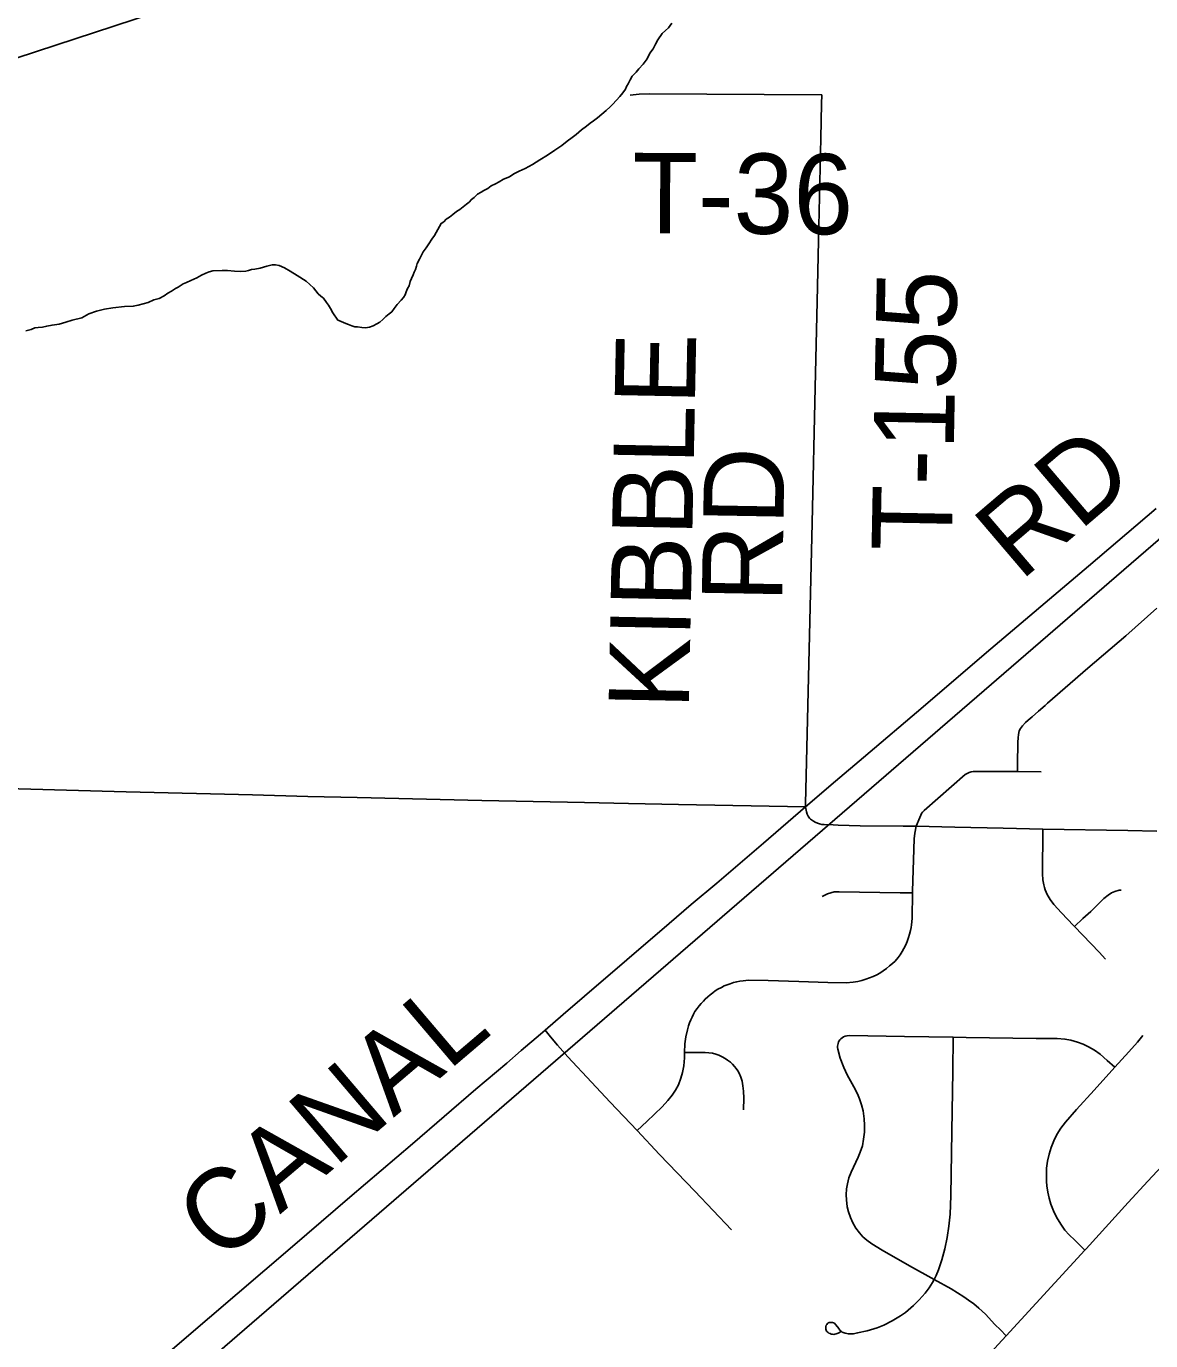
# Model space of a CAD drawing. Extents: x -483 to 680, y 0 to 440.
# Drawn here: x 200.49 to 240.28, y 283.88 to 330.39 of the extents above; entities that cross this region are included whole.
import ezdxf

# ---------------------------------------------------------------- set-up
doc = ezdxf.new("R2010")
doc.units = 0
for name, color, linetype in [('GM_X_City_Street', 7, 'Continuous'), ('GM_X_County_Road', 7, 'Continuous'), ('GM_X_County_Road_Text', 7, 'Continuous'), ('GM_X_Minor_River', 7, 'Continuous'), ('GM_X_Rail_Line', 7, 'Continuous'), ('GM_X_State_Route', 7, 'Continuous'), ('GM_X_Township_Road', 7, 'Continuous'), ('GM_X_Township_Road_Text', 7, 'Continuous')]:
    doc.layers.add(name, color=color, linetype=linetype)

msp = doc.modelspace()

# ---------------------------------------------------------------- linework, layer by layer
at = {"layer": 'GM_X_City_Street'}
for points in [[(235.562, 304.018), (235.565, 304.383), (235.569, 304.938), (235.576, 305.061), (235.584, 305.214), (235.596, 305.337), (235.627, 305.457), (235.665, 305.541), (235.737, 305.643), (235.845, 305.754), (235.936, 305.835), (236.076, 305.956), (236.31, 306.16), (236.536, 306.363), (236.626, 306.441), (238.047, 307.678), (239.394, 308.823), (240.497, 309.804)], [(231.975, 302.085), (232.102, 302.398), (232.143, 302.484), (232.172, 302.533), (232.205, 302.583), (232.258, 302.64), (233.713, 303.912), (233.783, 303.957), (233.849, 303.986), (233.923, 304.007), (233.992, 304.02), (234.095, 304.023), (235.107, 304.024), (235.562, 304.018), (236.396, 304.007)], [(228.062, 302.769), (228.096, 302.594), (228.121, 302.517), (228.16, 302.439), (228.209, 302.369), (228.239, 302.339), (228.272, 302.312), (228.345, 302.265), (228.408, 302.229), (228.485, 302.194), (228.559, 302.169), (228.64, 302.152), (228.721, 302.145), (229.039, 302.132), (229.214, 302.123), (229.993, 302.105), (231.516, 302.089), (231.975, 302.085), (233.349, 302.054), (235.058, 302.014), (236.465, 301.988), (239.471, 301.934), (240.496, 301.913)], [(222.109, 291.316), (222.45, 291.643), (222.988, 292.158), (223.197, 292.383), (223.349, 292.575), (223.466, 292.753), (223.564, 292.942), (223.655, 293.168), (223.712, 293.373), (223.754, 293.614), (223.776, 293.889), (223.784, 294.083), (223.796, 294.387), (223.828, 294.638), (223.882, 294.885), (223.923, 295.022), (223.958, 295.127), (224.002, 295.233), (224.049, 295.33), (224.099, 295.439), (224.152, 295.529), (224.228, 295.635), (224.302, 295.732), (224.371, 295.816), (224.448, 295.899), (224.512, 295.969), (224.607, 296.054), (224.686, 296.121), (224.781, 296.192), (224.871, 296.258), (224.963, 296.321), (225.086, 296.385), (225.189, 296.435), (225.398, 296.514), (225.516, 296.552), (225.629, 296.585), (225.74, 296.605), (225.86, 296.622), (226.051, 296.636), (226.737, 296.624), (227.825, 296.59), (228.85, 296.562), (229.501, 296.55), (229.744, 296.567), (229.909, 296.589), (230.051, 296.624), (230.201, 296.671), (230.326, 296.717), (230.452, 296.768), (230.583, 296.828), (230.694, 296.892), (230.813, 296.968), (230.926, 297.052), (231.039, 297.145), (231.138, 297.231), (231.229, 297.316), (231.337, 297.441), (231.413, 297.542), (231.487, 297.657), (231.547, 297.764), (231.609, 297.89), (231.655, 298.011), (231.709, 298.155), (231.746, 298.272), (231.781, 298.4), (231.801, 298.505), (231.814, 298.597), (231.828, 298.71), (231.836, 298.829), (231.851, 299.727), (231.852, 299.787), (231.904, 301.638), (231.93, 301.838), (231.975, 302.085)], [(238.682, 297.383), (238.447, 297.63), (237.575, 298.539), (237.544, 298.571), (237.116, 299.019), (236.849, 299.318), (236.724, 299.49), (236.618, 299.673), (236.546, 299.838), (236.518, 299.917), (236.493, 300.012), (236.46, 300.19), (236.442, 300.401), (236.446, 300.771), (236.458, 301.579), (236.465, 301.988)], [(228.652, 299.595), (228.841, 299.691), (228.954, 299.736), (229.072, 299.76), (229.258, 299.769), (231.408, 299.734), (231.851, 299.727)], [(237.575, 298.539), (237.88, 298.822), (238.152, 299.075), (238.622, 299.525), (238.765, 299.643), (238.894, 299.727), (239.007, 299.777), (239.157, 299.819), (239.226, 299.83)], [(225.448, 287.803), (224.146, 289.178), (222.901, 290.477), (222.109, 291.316), (221.154, 292.327), (220.495, 293.028), (219.655, 293.932), (219.285, 294.335), (219.042, 294.631), (218.846, 294.87)], [(229.308, 284.207), (229.27, 284.177), (229.221, 284.148), (229.188, 284.135), (229.144, 284.123), (229.098, 284.114), (229.059, 284.109), (229.013, 284.112), (228.966, 284.12), (228.929, 284.133), (228.892, 284.149), (228.861, 284.17), (228.832, 284.194), (228.81, 284.225), (228.794, 284.254), (228.784, 284.29), (228.78, 284.322), (228.782, 284.356), (228.786, 284.391), (228.797, 284.431), (228.815, 284.463), (228.838, 284.49), (228.869, 284.512), (228.901, 284.526), (228.94, 284.533), (228.978, 284.533), (229.018, 284.529), (229.052, 284.52), (229.083, 284.505), (229.129, 284.463), (229.196, 284.37), (229.238, 284.313), (229.267, 284.274), (229.31, 284.228), (229.335, 284.205), (229.363, 284.187), (229.396, 284.171), (229.426, 284.157), (229.467, 284.145), (229.525, 284.133), (229.577, 284.126), (229.627, 284.123), (229.676, 284.123), (229.761, 284.132), (229.907, 284.159), (230.241, 284.235), (230.598, 284.341), (230.829, 284.433), (231.133, 284.589), (231.429, 284.76), (231.605, 284.887), (231.888, 285.13), (232.086, 285.327), (232.291, 285.561), (232.44, 285.76), (232.555, 285.944), (232.612, 286.051), (232.685, 286.191), (232.77, 286.391), (232.885, 286.746), (232.988, 287.136), (233.072, 287.532), (233.133, 287.931), (233.177, 288.364), (233.209, 289.014), (233.242, 291.282), (233.27, 293.426), (233.287, 294.625)], [(235.164, 284.056), (234.96, 284.263), (234.764, 284.463), (234.428, 284.826), (234.192, 285.041), (234.015, 285.186), (233.835, 285.319), (233.664, 285.434), (233.212, 285.714), (232.612, 286.051), (231.746, 286.537), (230.775, 287.092), (230.404, 287.315), (230.231, 287.439), (230.096, 287.56), (229.975, 287.695), (229.848, 287.867), (229.74, 288.05), (229.652, 288.244), (229.581, 288.444), (229.54, 288.621), (229.508, 288.863), (229.501, 289.045), (229.514, 289.258), (229.544, 289.437), (229.598, 289.643), (229.672, 289.843), (229.929, 290.373), (230.001, 290.551), (230.074, 290.782), (230.114, 291.011), (230.144, 291.262), (230.155, 291.514), (230.143, 291.736), (230.099, 292.017), (230.047, 292.233), (229.975, 292.442), (229.903, 292.616), (229.774, 292.868), (229.54, 293.293), (229.415, 293.555), (229.29, 293.877), (229.204, 294.195), (229.199, 294.253), (229.199, 294.3), (229.204, 294.357), (229.212, 294.401), (229.235, 294.458), (229.277, 294.526), (229.315, 294.561)], [(229.315, 294.561), (229.358, 294.599), (229.407, 294.635), (229.465, 294.66), (229.531, 294.676), (229.613, 294.687), (231.569, 294.653), (233.287, 294.625), (233.742, 294.617), (236.225, 294.582), (236.968, 294.573), (237.243, 294.555), (237.452, 294.517), (237.687, 294.452), (237.887, 294.378), (238.079, 294.287), (238.288, 294.162), (238.485, 294.019), (238.739, 293.794), (239.005, 293.559)], [(237.947, 287.086), (237.588, 287.437), (237.386, 287.634), (237.24, 287.8), (237.093, 288.007), (236.948, 288.25), (236.837, 288.477), (236.744, 288.711), (236.68, 288.924), (236.634, 289.14), (236.604, 289.358), (236.591, 289.514), (236.583, 289.734), (236.584, 289.828), (236.594, 289.986), (236.628, 290.236), (236.681, 290.482), (236.753, 290.724), (236.846, 290.96), (236.96, 291.185), (237.094, 291.398), (237.263, 291.62), (237.651, 292.062), (238.272, 292.751), (239.005, 293.559), (239.501, 294.106), (239.807, 294.449), (240.003, 294.678)], [(225.869, 292.048), (225.882, 292.464), (225.873, 292.713), (225.85, 292.907), (225.818, 293.07), (225.773, 293.209), (225.71, 293.345), (225.662, 293.437), (225.61, 293.512), (225.55, 293.588), (225.482, 293.664), (225.403, 293.737), (225.306, 293.81), (225.221, 293.868), (225.108, 293.929), (224.995, 293.983), (224.885, 294.026), (224.77, 294.056), (224.647, 294.07), (224.515, 294.078), (224.207, 294.08), (223.784, 294.083)]]:
    msp.add_lwpolyline(points, dxfattribs=at)
at = {"layer": 'GM_X_County_Road'}
for points in [[(228.062, 302.769), (229.121, 303.679), (230.118, 304.522), (232.226, 306.314), (234.469, 308.236), (238.071, 311.294), (240.468, 313.323)], [(218.846, 294.87), (219.488, 295.426), (220.246, 296.07), (223.238, 298.646), (224.018, 299.314), (224.922, 300.074), (226.574, 301.491), (228.062, 302.769)], [(199.794, 278.543), (201.845, 280.377), (203.117, 281.425), (204.923, 282.948), (206.976, 284.71), (209.908, 287.214), (211.937, 288.957), (214.16, 290.855), (216.4, 292.781), (217.497, 293.705), (218.002, 294.15), (218.689, 294.733), (218.846, 294.87)]]:
    msp.add_lwpolyline(points, dxfattribs=at)
at = {"layer": 'GM_X_Minor_River'}
for points in [[(195.284, 273.119), (289.59, 354.596)], [(223.328, 330.503), (223.209, 330.335), (223.112, 330.243), (222.996, 330.132), (222.838, 329.908), (222.758, 329.758), (222.678, 329.589), (222.56, 329.44), (222.46, 329.234), (222.323, 329.047), (222.167, 328.88), (222.069, 328.769), (221.932, 328.62), (221.853, 328.49), (221.793, 328.358), (221.733, 328.265), (221.693, 328.171), (221.595, 328.04), (221.496, 327.91), (221.243, 327.631), (221.145, 327.539), (221.009, 327.409), (220.854, 327.28), (220.699, 327.151), (220.563, 327.041), (220.447, 326.968), (220.312, 326.857), (220.138, 326.729), (219.943, 326.563), (219.808, 326.452), (219.633, 326.324), (219.44, 326.177), (219.189, 326.012), (218.937, 325.829), (218.667, 325.665), (218.397, 325.5), (218.147, 325.355), (217.936, 325.265), (217.743, 325.175), (217.589, 325.065), (217.378, 324.976), (217.223, 324.884), (217.089, 324.812), (216.935, 324.74), (216.819, 324.648), (216.684, 324.575), (216.588, 324.521), (216.453, 324.448), (216.336, 324.337), (216.239, 324.264), (216.161, 324.171), (216.064, 324.097), (215.948, 324.005), (215.832, 323.913), (215.716, 323.84), (215.58, 323.73), (215.464, 323.638), (215.348, 323.565), (215.27, 323.472), (215.173, 323.417), (214.935, 322.986), (214.836, 322.856), (214.737, 322.687), (214.639, 322.557), (214.54, 322.408), (214.481, 322.295), (214.401, 322.145), (214.321, 321.995), (214.3, 321.901), (214.259, 321.788), (214.219, 321.694), (214.178, 321.6)], [(214.178, 321.6), (214.118, 321.469), (214.077, 321.356), (214.036, 321.205), (213.976, 321.111), (213.935, 320.999), (213.895, 320.886), (213.835, 320.792), (213.757, 320.699), (213.62, 320.551), (213.503, 320.402), (213.424, 320.29), (213.327, 320.216), (213.211, 320.124), (213.113, 320.013), (212.997, 319.921), (212.901, 319.866), (212.766, 319.794), (212.631, 319.74), (212.498, 319.725), (212.365, 319.728), (212.214, 319.751), (212.119, 319.753), (212.006, 319.794), (211.893, 319.835), (211.743, 319.896), (211.611, 319.956), (211.517, 319.996), (211.334, 320.248), (211.261, 320.402), (211.188, 320.517), (211.115, 320.614), (211.005, 320.769), (210.912, 320.847), (210.819, 320.926), (210.653, 321.139), (210.393, 321.373), (210.075, 321.571), (209.832, 321.729), (209.626, 321.848), (209.438, 321.929), (209.306, 321.951), (209.192, 321.954), (209.001, 321.902), (208.771, 321.832), (208.58, 321.799), (208.466, 321.783), (208.351, 321.748), (208.256, 321.731), (208.084, 321.717), (207.857, 321.722), (207.61, 321.747), (207.421, 321.752), (207.097, 321.741), (206.964, 321.707), (206.848, 321.653), (206.695, 321.581), (206.521, 321.49), (206.31, 321.401), (206.157, 321.329), (206.041, 321.274), (205.868, 321.165), (205.771, 321.11), (205.636, 321.019), (205.501, 320.946), (205.366, 320.855), (205.193, 320.764), (205.002, 320.712), (204.809, 320.622), (204.446, 320.517), (204.274, 320.484), (203.97, 320.472), (203.551, 320.426), (203.265, 320.376), (202.978, 320.308), (202.71, 320.219), (202.459, 320.074), (202.115, 319.988), (201.886, 319.917), (201.656, 319.847), (201.408, 319.816), (201.218, 319.782), (201.065, 319.748), (200.913, 319.733), (200.798, 319.717), (200.664, 319.663), (200.473, 319.611)]]:
    msp.add_lwpolyline(points, dxfattribs=at)
at = {"layer": 'GM_X_Rail_Line'}
msp.add_lwpolyline([(52.231, 281.076), (127.278, 305.392), (222.338, 336.549), (257.887, 348.093), (262.457, 349.692), (266.922, 351.391), (271.85, 353.786), (276.063, 355.851), (279.587, 357.722), (282.074, 359.273), (284.73, 360.909), (286.844, 362.348), (291.566, 365.767), (297.907, 370.986), (306.481, 378.212), (309.709, 381.296), (311.628, 383.535), (313.46, 385.542), (315.408, 389.44), (316.608, 391.805), (318.711, 395.95)], dxfattribs=at)
at = {"layer": 'GM_X_State_Route'}
msp.add_lwpolyline([(234.647, 283.487), (234.88, 283.747), (235.164, 284.056), (237.947, 287.086), (237.994, 287.136), (239.481, 288.775), (240.176, 289.534), (241.502, 290.96), (242.598, 292.173), (243.621, 293.317), (244.177, 293.985), (244.568, 294.473), (245.171, 295.278), (245.647, 295.945), (246.497, 297.164), (247.202, 298.233), (248.207, 299.705), (248.379, 299.957)], dxfattribs=at)
at = {"layer": 'GM_X_Township_Road'}
for points in [[(221.853, 327.958), (222.172, 327.992), (222.528, 328), (228.64, 327.965)], [(228.062, 302.769), (228.065, 302.874), (228.299, 312.822), (228.408, 317.607), (228.478, 320.652), (228.523, 322.796), (228.599, 326.432), (228.631, 327.643), (228.64, 327.965)], [(177.765, 303.951), (177.987, 303.95), (178.546, 303.947), (181.187, 303.882), (182.927, 303.836), (184.791, 303.785), (187.929, 303.709), (193.243, 303.587), (195.045, 303.547), (196.847, 303.501), (204.024, 303.301), (208.498, 303.193), (210.455, 303.142), (212.195, 303.105), (216.607, 303.002), (220.243, 302.924), (221.797, 302.889), (223.568, 302.854), (228.062, 302.769)]]:
    msp.add_lwpolyline(points, dxfattribs=at)

# ---------------------------------------------------------------- texts
at = {"layer": 'GM_X_County_Road_Text'}
for s, rotation, p in [('RD', 40.4399, (235.666, 310.73)), ('CANAL', 40.3875, (207.376, 286.567))]:
    msp.add_text(s, height=2.8409, rotation=rotation, dxfattribs=at).set_placement(p)
at = {"layer": 'GM_X_Township_Road_Text'}
for s, rotation, p in [('T-36', 359.6442, (221.927, 323.074)), ('T-155', 88.8774, (233.237, 311.804)), ('KIBBLE', 88.8578, (223.933, 306.207)), ('RD', 89.0127, (227.232, 309.986))]:
    msp.add_text(s, height=2.8409, rotation=rotation, dxfattribs=at).set_placement(p)

doc.saveas('drawing.dxf')
